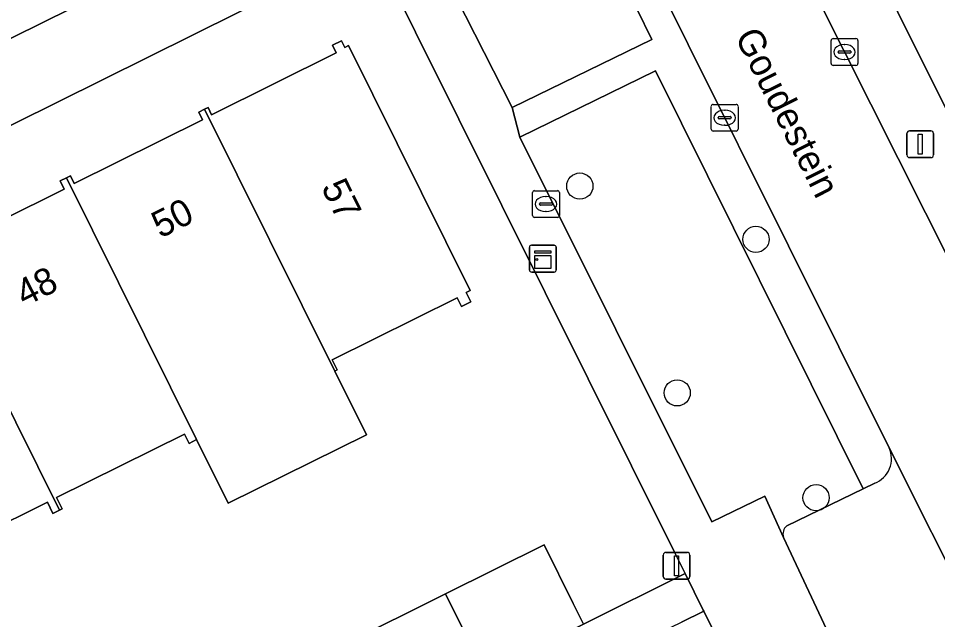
# Model space of a CAD drawing. Extents: x 157793 to 159380, y 380877 to 382313.
# Drawn here: x 158297.85 to 158332.13, y 381447.24 to 381469.68 of the extents above; entities that cross this region are included whole.
import ezdxf

# ---------------------------------------------------------------- set-up
doc = ezdxf.new("R2010")
doc.units = 0
for name, color, linetype in [('IMGEO_Boom', 7, 'Continuous'), ('IMGEO_Erf', 7, 'Continuous'), ('IMGEO_Groenvoorziening', 7, 'Continuous'), ('IMGEO_Kast', 7, 'Continuous'), ('IMGEO_Kolk', 7, 'Continuous'), ('IMGEO_Lichtmast', 7, 'Continuous'), ('IMGEO_Openbare_ruimte_label', 7, 'Continuous'), ('IMGEO_Pand', 7, 'Continuous'), ('IMGEO_Pand_nummerreeks', 7, 'Continuous'), ('IMGEO_Parkeervlak_open', 7, 'Continuous'), ('IMGEO_Rijbaan_lokaal_open', 7, 'Continuous'), ('IMGEO_Voetpad_open', 7, 'Continuous')]:
    doc.layers.add(name, color=color, linetype=linetype)

msp = doc.modelspace()

# ---------------------------------------------------------------- linework, layer by layer
at = {"layer": 'IMGEO_Boom'}
for centre in [(158318.789, 381463.419), (158325.358, 381461.432), (158322.421, 381455.703), (158327.6, 381451.791)]:
    msp.add_circle(centre, 0.489, dxfattribs=at)
at = {"layer": 'IMGEO_Erf'}
for points in [[(158326.548, 381478.159), (158336.768, 381457.628)], [(158294.659, 381434.559), (158298.412, 381436.409), (158299.747, 381433.7), (158300.006, 381433.828), (158298.544, 381436.794), (158301.131, 381438.229), (158300.877, 381438.74), (158299.696, 381441.116), (158303.519, 381443.016), (158307.192, 381444.842), (158308.281, 381442.652), (158308.627, 381441.956), (158311.428, 381443.349), (158309.959, 381446.304), (158313.781, 381448.204), (158317.455, 381450.03), (158318.544, 381447.84), (158318.924, 381447.075), (158322.717, 381448.96), (158322.317, 381449.765), (158311.062, 381472.396), (158255.837, 381444.973)], [(158294.828, 381460.956), (158299.565, 381463.31), (158299.413, 381463.616), (158299.641, 381463.73), (158299.796, 381463.807), (158299.938, 381463.52), (158304.717, 381465.896), (158304.576, 381466.18), (158304.791, 381466.287), (158304.924, 381466.353), (158305.06, 381466.08), (158309.703, 381468.388), (158309.562, 381468.673), (158309.896, 381468.839), (158310.02, 381468.59), (158310.165, 381468.661), (158314.704, 381459.528), (158314.55, 381459.452), (158314.728, 381459.095), (158314.378, 381458.921), (158314.215, 381459.247), (158309.557, 381456.931), (158309.743, 381456.557), (158309.651, 381456.511), (158310.829, 381454.141), (158305.68, 381451.582), (158304.499, 381453.958), (158304.217, 381453.818), (158304.045, 381454.164), (158299.277, 381451.794), (158299.487, 381451.372), (158299.388, 381451.323), (158299.142, 381451.201), (158298.932, 381451.623), (158294.03, 381449.186)], [(158328.448, 381437.436), (158323.416, 381447.554), (158322.584, 381447.151)]]:
    msp.add_lwpolyline(points, dxfattribs=at)
at = {"layer": 'IMGEO_Groenvoorziening'}
for points in [[(158304.977, 381480.342), (158304.861, 381480.266), (158297.419, 381475.832), (158294.066, 381473.665), (158272.57, 381458.87), (158273.457, 381457.008), (158309.727, 381474.963)], [(158321.608, 381467.725), (158316.546, 381465.245), (158323.708, 381450.89), (158325.692, 381451.847), (158326.38, 381450.312)], [(158326.504, 381450.741), (158329.353, 381452.122), (158321.608, 381467.725)]]:
    msp.add_lwpolyline(points, dxfattribs=at)
msp.add_lwpolyline([(158318.119, 381475.762), (158312.782, 381473.207), (158316.267, 381466.353), (158321.475, 381468.887)], close=True, dxfattribs=at)
msp.add_arc((158326.783, 381450.428), 0.419, 131.6903, 196.0664, dxfattribs=at)
at = {"layer": 'IMGEO_Kast'}
for p, q in [((158316.911, 381460.287), (158316.911, 381461.128)), ((158316.911, 381461.128), (158316.911, 381460.287)), ((158316.986, 381461.212), (158317.827, 381461.212)), ((158317.827, 381461.212), (158316.986, 381461.212)), ((158317.911, 381461.137), (158317.911, 381460.296)), ((158317.911, 381460.296), (158317.911, 381461.137)), ((158317.836, 381460.212), (158316.995, 381460.212)), ((158316.995, 381460.212), (158317.836, 381460.212))]:
    msp.add_line(p, q, dxfattribs=at)
for points in [[(158317.106, 381461.002), (158317.706, 381461.002), (158317.706, 381460.917), (158317.106, 381460.917), (158317.106, 381461.002)], [(158317.106, 381460.827), (158317.706, 381460.827), (158317.706, 381460.338), (158317.106, 381460.338), (158317.106, 381460.827)]]:
    msp.add_lwpolyline(points, dxfattribs=at)
msp.add_circle((158317.19, 381460.676), 0.0377, dxfattribs=at)
for centre, start, end in [((158316.989, 381461.134), 92.4484, 184.2845), ((158316.989, 381461.134), 92.4484, 184.2845), ((158317.833, 381461.134), 2.4484, 94.2845), ((158317.833, 381461.134), 2.4484, 94.2845), ((158316.989, 381460.29), 182.4484, 274.2845), ((158316.989, 381460.29), 182.4484, 274.2845), ((158317.833, 381460.29), 272.4484, 4.2845), ((158317.833, 381460.29), 272.4484, 4.2845)]:
    msp.add_arc(centre, 0.0779, start, end, dxfattribs=at)
at = {"layer": 'IMGEO_Kolk'}
for p, q in [((158328.235, 381468.921), (158329.087, 381468.921)), ((158328.16, 381467.995), (158328.16, 381468.847)), ((158328.648, 381468.701), (158328.673, 381468.701)), ((158329.161, 381468.847), (158329.161, 381467.995)), ((158328.419, 381468.415), (158328.419, 381468.427)), ((158328.857, 381468.378), (158328.459, 381468.378)), ((158328.462, 381468.464), (158328.86, 381468.464)), ((158328.903, 381468.427), (158328.903, 381468.415)), ((158329.087, 381467.921), (158328.235, 381467.921)), ((158328.671, 381468.141), (158328.646, 381468.141)), ((158323.691, 381465.543), (158323.691, 381466.395)), ((158323.766, 381466.469), (158324.618, 381466.469)), ((158324.179, 381466.249), (158324.204, 381466.249)), ((158324.692, 381466.395), (158324.692, 381465.543)), ((158323.95, 381465.963), (158323.95, 381465.975)), ((158324.388, 381465.926), (158323.99, 381465.926)), ((158323.993, 381466.012), (158324.391, 381466.012)), ((158324.434, 381465.975), (158324.434, 381465.963)), ((158324.618, 381465.469), (158323.766, 381465.469)), ((158324.202, 381465.689), (158324.177, 381465.689)), ((158317.026, 381462.322), (158317.026, 381463.174)), ((158317.101, 381463.248), (158317.953, 381463.248)), ((158318.027, 381463.174), (158318.027, 381462.322)), ((158317.285, 381462.742), (158317.285, 381462.754)), ((158317.328, 381462.791), (158317.726, 381462.791)), ((158317.514, 381463.028), (158317.539, 381463.028)), ((158317.769, 381462.754), (158317.769, 381462.742)), ((158317.723, 381462.705), (158317.325, 381462.705)), ((158317.537, 381462.468), (158317.512, 381462.468)), ((158317.953, 381462.248), (158317.101, 381462.248))]:
    msp.add_line(p, q, dxfattribs=at)
for points in [[(158328.235, 381468.921), (158329.087, 381468.921)], [(158328.16, 381467.995), (158328.16, 381468.847)], [(158329.161, 381468.847), (158329.161, 381467.995)], [(158329.087, 381467.921), (158328.235, 381467.921)], [(158323.691, 381465.543), (158323.691, 381466.395)], [(158323.766, 381466.469), (158324.618, 381466.469)], [(158324.692, 381466.395), (158324.692, 381465.543)], [(158324.618, 381465.469), (158323.766, 381465.469)], [(158317.026, 381462.322), (158317.026, 381463.174)], [(158317.101, 381463.248), (158317.953, 381463.248)], [(158318.027, 381463.174), (158318.027, 381462.322)], [(158317.953, 381462.248), (158317.101, 381462.248)]]:
    msp.add_lwpolyline(points, dxfattribs=at)
for centre, radius, start, end in [((158328.237, 381468.845), 0.0765, 91.552, 178.448), ((158328.237, 381468.845), 0.0765, 91.552, 178.448), ((158329.085, 381468.845), 0.0765, 1.552, 88.448), ((158329.085, 381468.845), 0.0765, 1.552, 88.448), ((158328.459, 381468.424), 0.0403, 85.8775, 175.7526), ((158328.456, 381468.414), 0.0366, 178.938, 274.7102), ((158328.86, 381468.421), 0.043, 264.8664, 352.4533), ((158328.864, 381468.426), 0.0386, 1.7309, 96.639), ((158328.237, 381467.997), 0.0765, 181.552, 268.448), ((158328.237, 381467.997), 0.0765, 181.552, 268.448), ((158329.085, 381467.997), 0.0765, 271.552, 358.448), ((158329.085, 381467.997), 0.0765, 271.552, 358.448), ((158323.768, 381466.393), 0.0765, 91.552, 178.448), ((158323.768, 381466.393), 0.0765, 91.552, 178.448), ((158324.616, 381466.393), 0.0765, 1.552, 88.448), ((158324.616, 381466.393), 0.0765, 1.552, 88.448), ((158323.99, 381465.972), 0.0403, 85.8775, 175.7526), ((158323.987, 381465.962), 0.0366, 178.938, 274.7102), ((158324.391, 381465.969), 0.043, 264.8664, 352.4533), ((158324.395, 381465.974), 0.0386, 1.7309, 96.639), ((158323.768, 381465.545), 0.0765, 181.552, 268.448), ((158323.768, 381465.545), 0.0765, 181.552, 268.448), ((158324.616, 381465.545), 0.0765, 271.552, 358.448), ((158324.616, 381465.545), 0.0765, 271.552, 358.448), ((158317.103, 381463.172), 0.0765, 91.552, 178.448), ((158317.103, 381463.172), 0.0765, 91.552, 178.448), ((158317.951, 381463.172), 0.0765, 1.552, 88.448), ((158317.951, 381463.172), 0.0765, 1.552, 88.448), ((158317.325, 381462.751), 0.0403, 85.8775, 175.7526), ((158317.322, 381462.741), 0.0366, 178.938, 274.7102), ((158317.726, 381462.748), 0.043, 264.8664, 352.4533), ((158317.73, 381462.753), 0.0386, 1.7309, 96.639), ((158317.103, 381462.324), 0.0765, 181.552, 268.448), ((158317.103, 381462.324), 0.0765, 181.552, 268.448), ((158317.951, 381462.324), 0.0765, 271.552, 358.448), ((158317.951, 381462.324), 0.0765, 271.552, 358.448)]:
    msp.add_arc(centre, radius, start, end, dxfattribs=at)
for centre, major_axis, ratio, start_param, end_param in [((158328.647, 381468.421), (-0.387, 0.002), 0.722429, 4.712389, 7.853982), ((158328.672, 381468.421), (-0.39, 0.002), 0.717154, 1.570796, 4.712389), ((158324.178, 381465.969), (-0.387, 0.002), 0.722429, 4.712389, 7.853982), ((158324.203, 381465.969), (-0.39, 0.002), 0.717154, 1.570796, 4.712389), ((158317.513, 381462.748), (-0.387, 0.002), 0.722429, 4.712389, 7.853982), ((158317.538, 381462.748), (-0.39, 0.002), 0.717154, 1.570796, 4.712389)]:
    msp.add_ellipse(centre, major_axis=major_axis, ratio=ratio, start_param=start_param, end_param=end_param, dxfattribs=at)
at = {"layer": 'IMGEO_Lichtmast'}
for p, q in [((158331.089, 381465.48), (158331.879, 381465.48)), ((158331.879, 381465.48), (158331.089, 381465.48)), ((158330.989, 381464.58), (158330.989, 381465.38)), ((158330.989, 381465.38), (158330.989, 381464.58)), ((158331.979, 381465.38), (158331.979, 381464.58)), ((158331.979, 381464.58), (158331.979, 381465.38)), ((158331.879, 381464.48), (158331.089, 381464.48)), ((158331.089, 381464.48), (158331.879, 381464.48)), ((158322, 381449.752), (158322.79, 381449.752)), ((158322.79, 381449.752), (158322, 381449.752)), ((158321.9, 381448.852), (158321.9, 381449.652)), ((158321.9, 381449.652), (158321.9, 381448.852)), ((158322.89, 381449.652), (158322.89, 381448.852)), ((158322.89, 381448.852), (158322.89, 381449.652)), ((158322.79, 381448.752), (158322, 381448.752)), ((158322, 381448.752), (158322.79, 381448.752))]:
    msp.add_line(p, q, dxfattribs=at)
for points in [[(158331.409, 381465.355), (158331.559, 381465.355), (158331.559, 381464.605), (158331.409, 381464.605), (158331.409, 381465.355)], [(158322.32, 381449.627), (158322.47, 381449.627), (158322.47, 381448.877), (158322.32, 381448.877), (158322.32, 381449.627)]]:
    msp.add_lwpolyline(points, dxfattribs=at)
for centre, start, end in [((158331.089, 381465.38), 90, 180), ((158331.089, 381465.38), 90, 180), ((158331.879, 381465.38), 0, 90), ((158331.879, 381465.38), 360, 90), ((158331.089, 381464.58), 180, 270), ((158331.089, 381464.58), 180, 270), ((158331.879, 381464.58), 270, 0), ((158331.879, 381464.58), 270, 0), ((158322, 381449.652), 90, 180), ((158322, 381449.652), 90, 180), ((158322.79, 381449.652), 0, 90), ((158322.79, 381449.652), 360, 90), ((158322, 381448.852), 180, 270), ((158322, 381448.852), 180, 270), ((158322.79, 381448.852), 270, 0), ((158322.79, 381448.852), 270, 0)]:
    msp.add_arc(centre, 0.1, start, end, dxfattribs=at)
at = {"layer": 'IMGEO_Pand'}
for points in [[(158304.791, 381466.287), (158309.651, 381456.511), (158309.743, 381456.557), (158309.557, 381456.931), (158314.215, 381459.247), (158314.378, 381458.921), (158314.728, 381459.095), (158314.55, 381459.452), (158314.704, 381459.528), (158310.165, 381468.661), (158310.02, 381468.59), (158309.896, 381468.839), (158309.562, 381468.673), (158309.703, 381468.388), (158305.06, 381466.08), (158304.924, 381466.353)], [(158304.791, 381466.287), (158304.576, 381466.18), (158304.717, 381465.896), (158299.938, 381463.52), (158299.796, 381463.807), (158299.641, 381463.73), (158304.499, 381453.958), (158305.68, 381451.582), (158310.829, 381454.141), (158309.651, 381456.511)], [(158299.388, 381451.323), (158299.487, 381451.372), (158299.277, 381451.794), (158304.045, 381454.164), (158304.217, 381453.818), (158304.499, 381453.958), (158299.641, 381463.73), (158299.413, 381463.616), (158299.565, 381463.31), (158294.828, 381460.956), (158294.686, 381461.242), (158294.501, 381461.15)], [(158294.501, 381461.15), (158294.349, 381461.075), (158294.491, 381460.788), (158289.826, 381458.469), (158289.677, 381458.77), (158289.355, 381458.61), (158289.525, 381458.267), (158289.313, 381458.161), (158290.98, 381454.806), (158291.183, 381454.907), (158294.03, 381449.186), (158298.932, 381451.623), (158299.142, 381451.201), (158299.388, 381451.323)], [(158313.781, 381448.204), (158315.25, 381445.249), (158318.924, 381447.075), (158318.544, 381447.84), (158317.455, 381450.03)], [(158313.781, 381448.204), (158309.959, 381446.304), (158311.428, 381443.349), (158315.25, 381445.249)]]:
    msp.add_lwpolyline(points, close=True, dxfattribs=at)
at = {"layer": 'IMGEO_Parkeervlak_open'}
for points in [[(158333.5, 381447.333), (158330.325, 381453.652)], [(158329.788, 381452.333), (158329.353, 381452.122), (158326.504, 381450.741)], [(158326.38, 381450.312), (158331.478, 381439.434)]]:
    msp.add_lwpolyline(points, dxfattribs=at)
for centre, radius, start, end in [((158329.428, 381453.248), 0.983, 291.4463, 24.2486), ((158326.783, 381450.428), 0.419, 131.6903, 196.0664)]:
    msp.add_arc(centre, radius, start, end, dxfattribs=at)
at = {"layer": 'IMGEO_Rijbaan_lokaal_open'}
msp.add_lwpolyline([(158338.824, 381448.203), (158323.507, 381478.675), (158321.13, 381483.404), (158316.611, 381481.195), (158319.073, 381476.25), (158330.325, 381453.652), (158333.5, 381447.333)], dxfattribs=at)
at = {"layer": 'IMGEO_Voetpad_open'}
for points in [[(158320.036, 381485.606), (158320.667, 381484.379), (158321.13, 381483.404), (158323.507, 381478.675), (158338.824, 381448.203)], [(158311.108, 381484.475), (158313.007, 381483.769), (158314.336, 381482.933), (158315.26, 381481.699), (158316.972, 381478.604), (158318.119, 381475.762), (158321.475, 381468.887), (158316.267, 381466.353), (158316.546, 381465.245), (158321.608, 381467.725), (158329.353, 381452.122), (158329.788, 381452.333)], [(158232.494, 381429.075), (158236.86, 381432.048), (158246.279, 381438.463), (158246.295, 381438.474), (158247.461, 381439.269), (158247.466, 381439.272), (158255.837, 381444.973), (158311.062, 381472.396), (158312.782, 381473.207), (158318.119, 381475.762), (158316.972, 381478.604), (158311.496, 381475.816), (158309.727, 381474.963), (158273.457, 381457.008), (158272.57, 381458.87)], [(158344.88, 381430.73), (158347.04, 381431.137), (158346.431, 381434.929), (158347.326, 381435.057), (158346.606, 381438.9), (158345.871, 381442.976), (158344.185, 381442.728), (158337.485, 381456.187), (158336.797, 381457.569), (158336.768, 381457.628), (158326.548, 381478.159)], [(158330.325, 381453.652), (158319.073, 381476.25)], [(158326.38, 381450.312), (158325.692, 381451.847), (158323.708, 381450.89), (158316.546, 381465.245), (158316.267, 381466.353), (158312.782, 381473.207), (158311.062, 381472.396), (158322.317, 381449.765), (158322.717, 381448.96), (158323.394, 381447.598), (158323.416, 381447.554), (158328.448, 381437.436), (158329.812, 381429.85), (158331.077, 381423.054), (158333.81, 381407.731), (158335.126, 381400.425), (158338.102, 381383.483), (158338.683, 381380.173), (158341.696, 381380.704)], [(158331.478, 381439.434), (158326.38, 381450.312)], [(158303.927, 381425.948), (158303.449, 381429.112), (158302.973, 381429.024), (158302.243, 381432.981), (158301.447, 381437.299), (158301.923, 381437.387), (158305.496, 381438.867), (158312.895, 381442.454), (158322.584, 381447.151), (158323.416, 381447.554), (158323.394, 381447.598), (158322.717, 381448.96), (158318.924, 381447.075), (158315.25, 381445.249), (158311.428, 381443.349), (158308.627, 381441.956), (158304.954, 381440.13), (158301.131, 381438.229), (158298.544, 381436.794), (158300.006, 381433.828), (158299.747, 381433.7), (158299.704, 381433.679), (158296.003, 381431.854)]]:
    msp.add_lwpolyline(points, dxfattribs=at)
msp.add_arc((158329.428, 381453.248), 0.983, 291.4463, 24.2486, dxfattribs=at)

# ---------------------------------------------------------------- texts
at = {"layer": 'IMGEO_Openbare_ruimte_label'}
msp.add_text('Goudestein', height=1, rotation=296.6932, dxfattribs=at).set_placement((158324.553, 381469.005))
at = {"layer": 'IMGEO_Pand_nummerreeks'}
for s, rotation, p in [('57', 296.4269, (158309.129, 381463.374)), ('50', 26.7285, (158303.147, 381461.454)), ('48', 26.7275, (158298.079, 381458.901))]:
    msp.add_text(s, height=1, rotation=rotation, dxfattribs=at).set_placement(p)

doc.saveas('drawing.dxf')
